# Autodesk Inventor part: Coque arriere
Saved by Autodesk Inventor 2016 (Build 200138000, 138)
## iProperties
Created: 2013-08
Part Number: Coque arriere
Material: Générique
Document SubType Name: Modeling
Designer: hilarion
Density: 1 g/cm^3
Appearance: Par défaut
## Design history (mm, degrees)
node "Coque arriere1"
node "Coque arriere"
node "Base1"
